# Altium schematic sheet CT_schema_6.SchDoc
size 368 x 336 mm
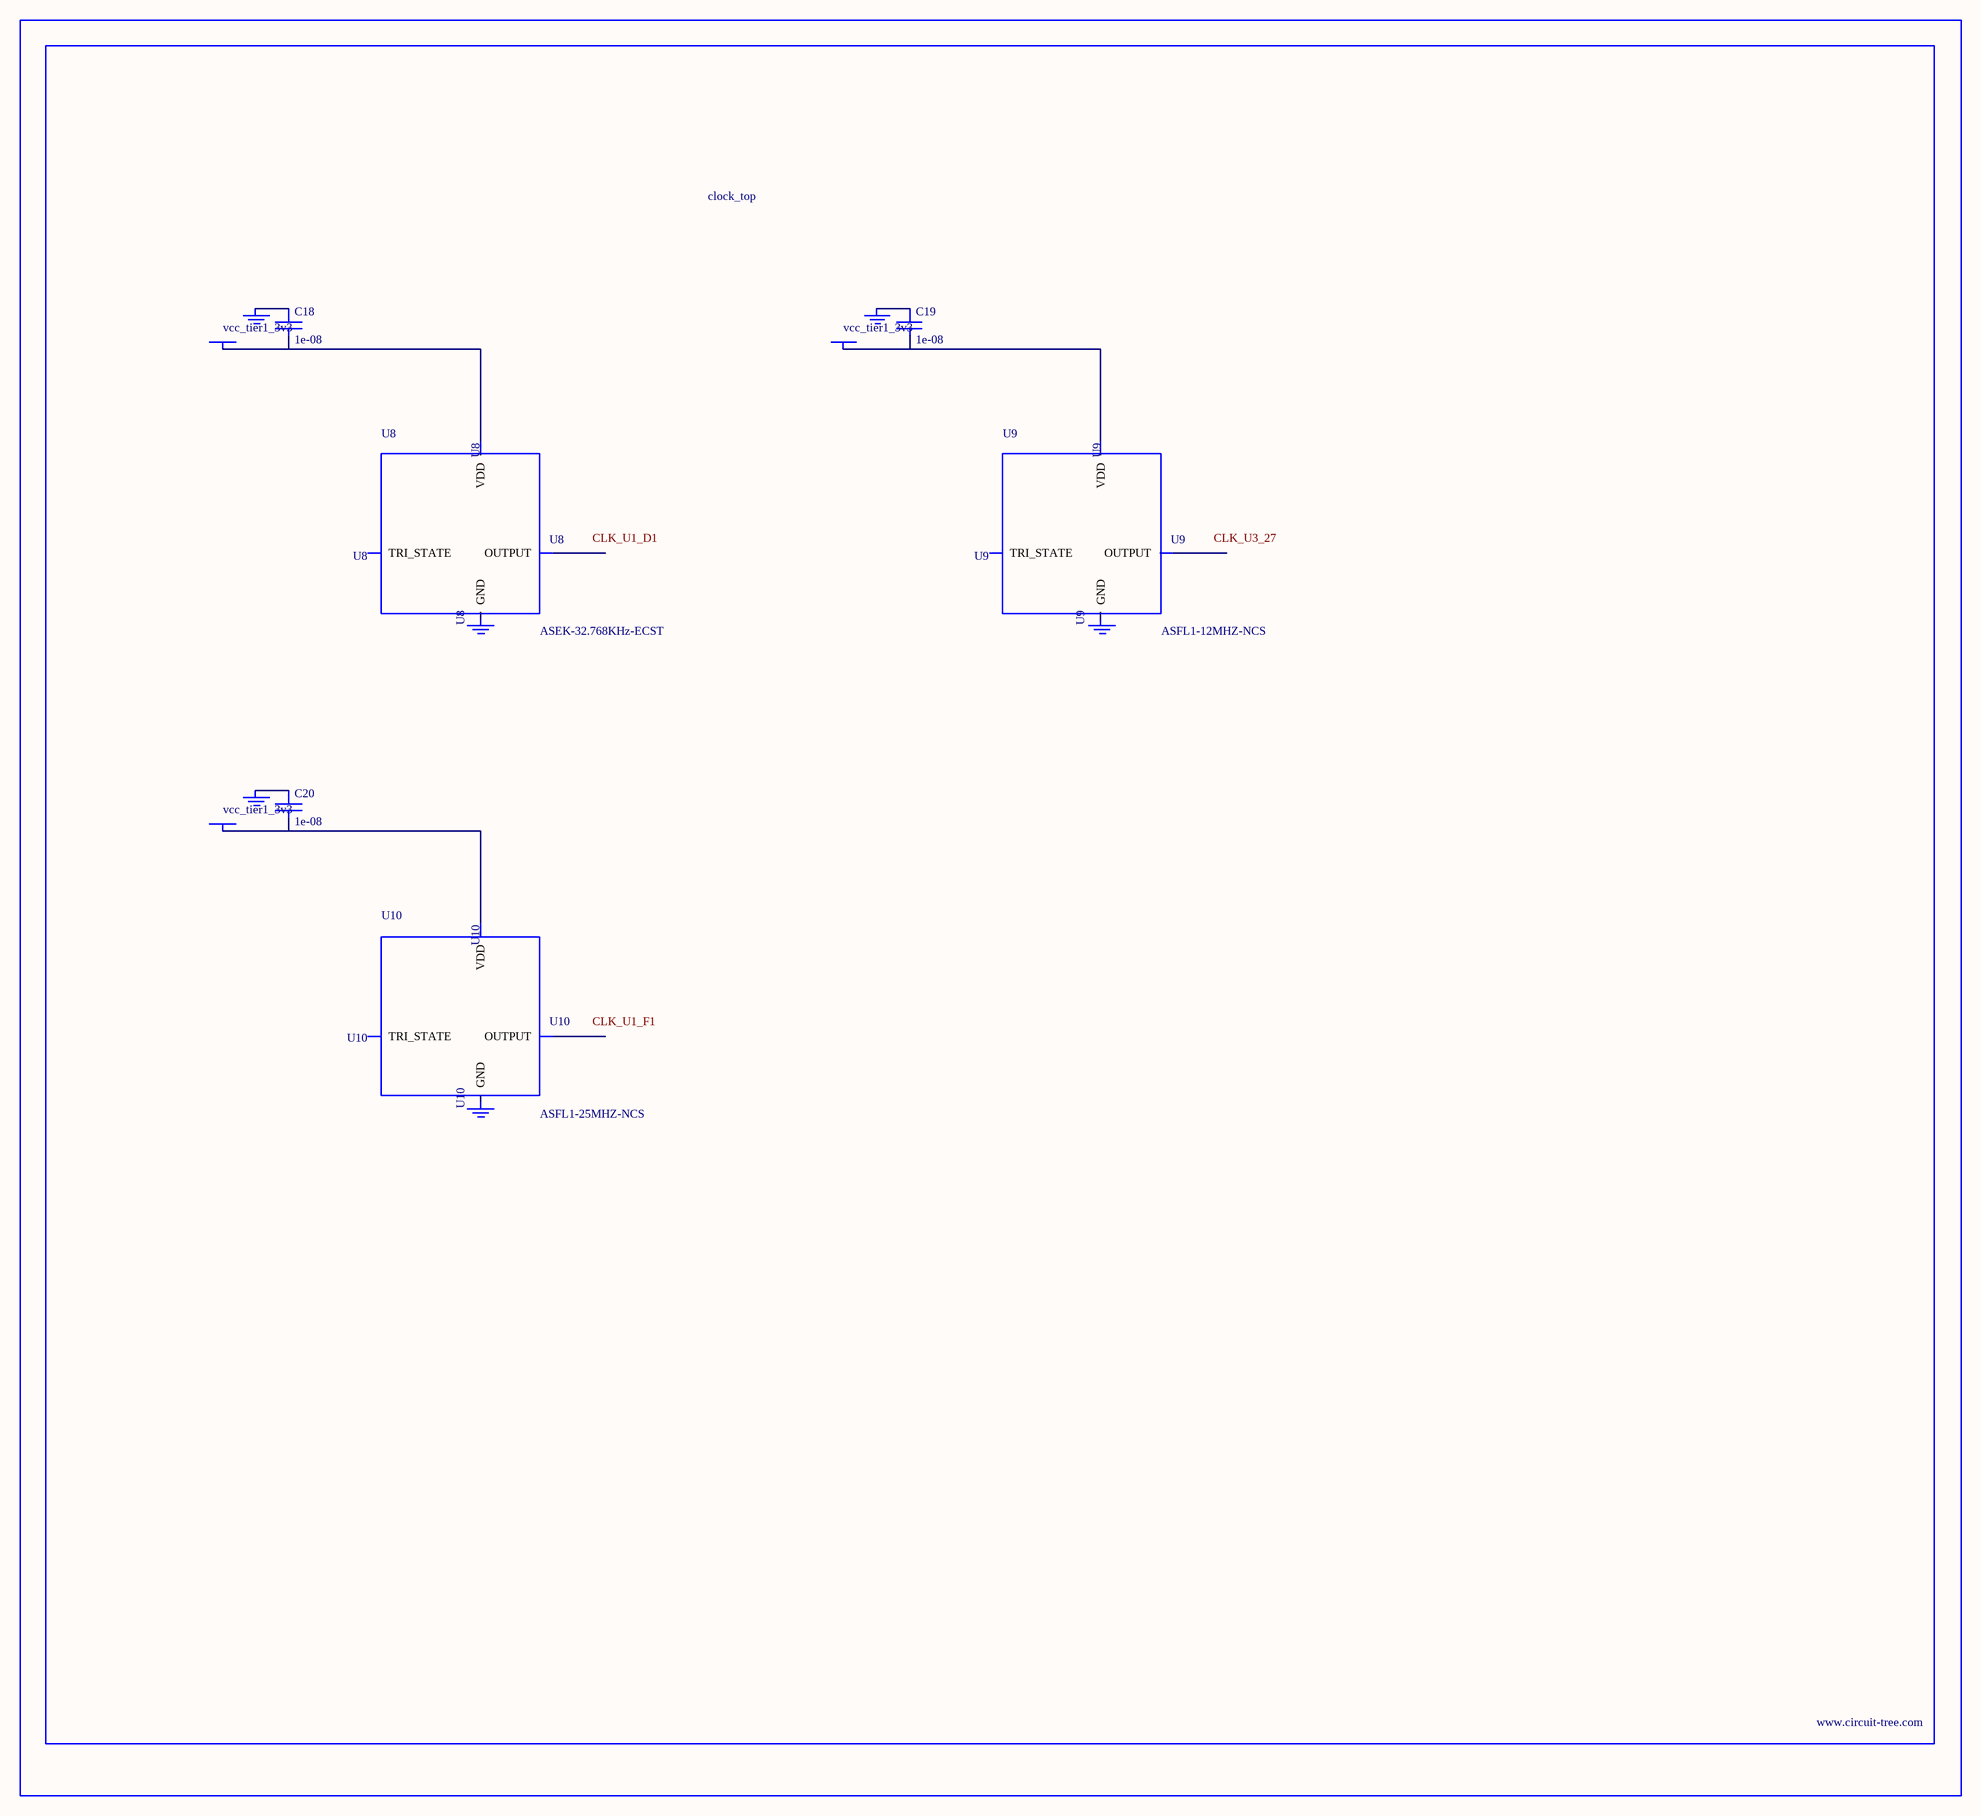
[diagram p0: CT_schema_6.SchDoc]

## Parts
BORDER5  (no value)
C18  1e-08  [C0402]
C19  1e-08  [C0402]
C20  1e-08  [C0402]
GND_INSTANCE_5_0  (no value)
GND_INSTANCE_5_1  (no value)
GND_INSTANCE_5_2  (no value)
GND_INSTANCE_5_3  (no value)
GND_INSTANCE_5_4  (no value)
GND_INSTANCE_5_5  (no value)
POWER_INSTANCE_5_0  vcc_tier1_3v3
POWER_INSTANCE_5_1  vcc_tier1_3v3
POWER_INSTANCE_5_2  vcc_tier1_3v3
U8  ASEK-32.768KHz-ECST  [ASEK]
U9  ASFL1-12MHZ-NCS  [ASFL1]
U10  ASFL1-25MHZ-NCS  [ASFL1]

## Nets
NetC18_1: C18.1 GND_INSTANCE_5_0.0(GND)
NetC18_2: C18.2 POWER_INSTANCE_5_0.0(PWR) U8.4(VDD)
NetC19_1: C19.1 GND_INSTANCE_5_2.0(GND)
NetC19_2: C19.2 POWER_INSTANCE_5_1.0(PWR) U9.4(VDD)
NetC20_1: C20.1 GND_INSTANCE_5_4.0(GND)
NetC20_2: C20.2 POWER_INSTANCE_5_2.0(PWR) U10.4(VDD)

Not connected (* = marked no-connect by the designer): GND_INSTANCE_5_1 0(GND); GND_INSTANCE_5_3 0(GND); GND_INSTANCE_5_5 0(GND); U8 1(TRI_STATE) 2(GND) 3(OUTPUT); U9 1(TRI_STATE) 2(GND) 3(OUTPUT); U10 1(TRI_STATE) 2(GND) 3(OUTPUT)

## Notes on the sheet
- Labels drawn without touching a wire or pin: CLK_U1_D1, CLK_U1_F1, CLK_U3_27

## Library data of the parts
BORDER5 = BORDER_PAGE5
C18-C20 = C0402C103K3RAC
GND_INSTANCE_5_0-GND_INSTANCE_5_5 = GND
POWER_INSTANCE_5_0-POWER_INSTANCE_5_2 = PWR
